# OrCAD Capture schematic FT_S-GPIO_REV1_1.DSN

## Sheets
1 INDEX: title: INDEX; rev: 1.0; note: 17 HaYetsira Street; note: Yokneam Illit, Israel 2069208
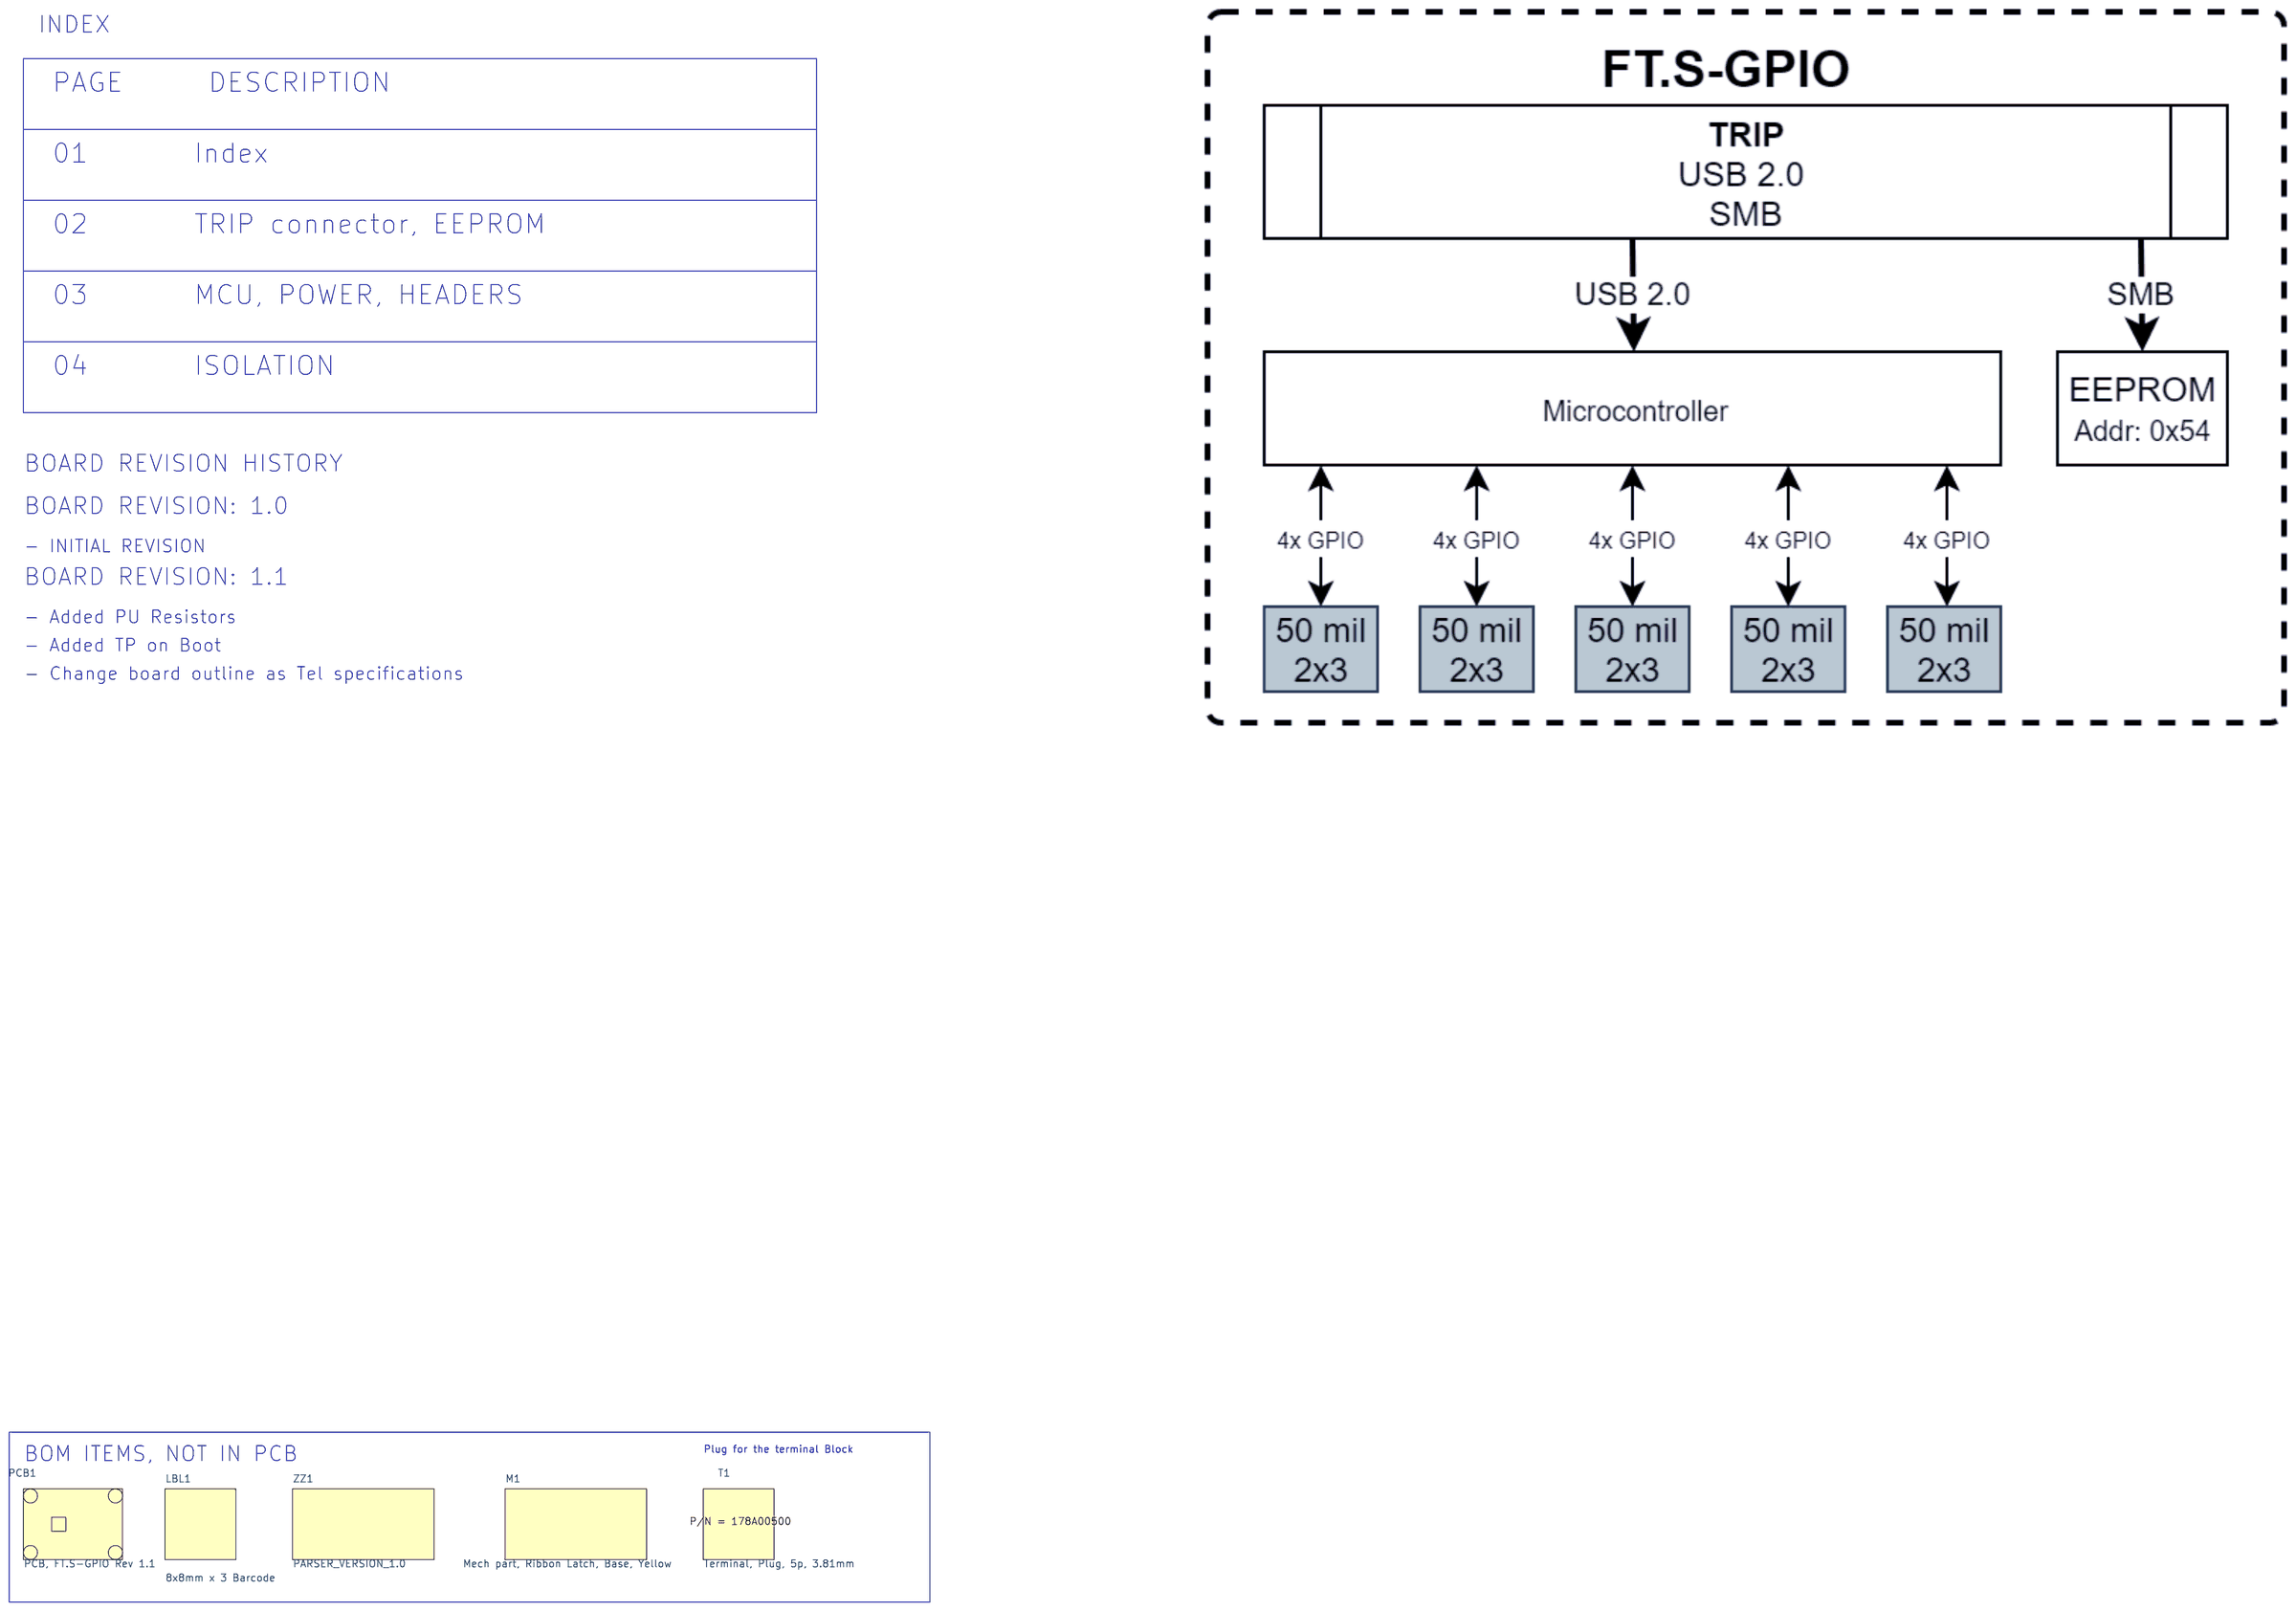
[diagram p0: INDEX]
2 CONN: size A3; title: 02- connector
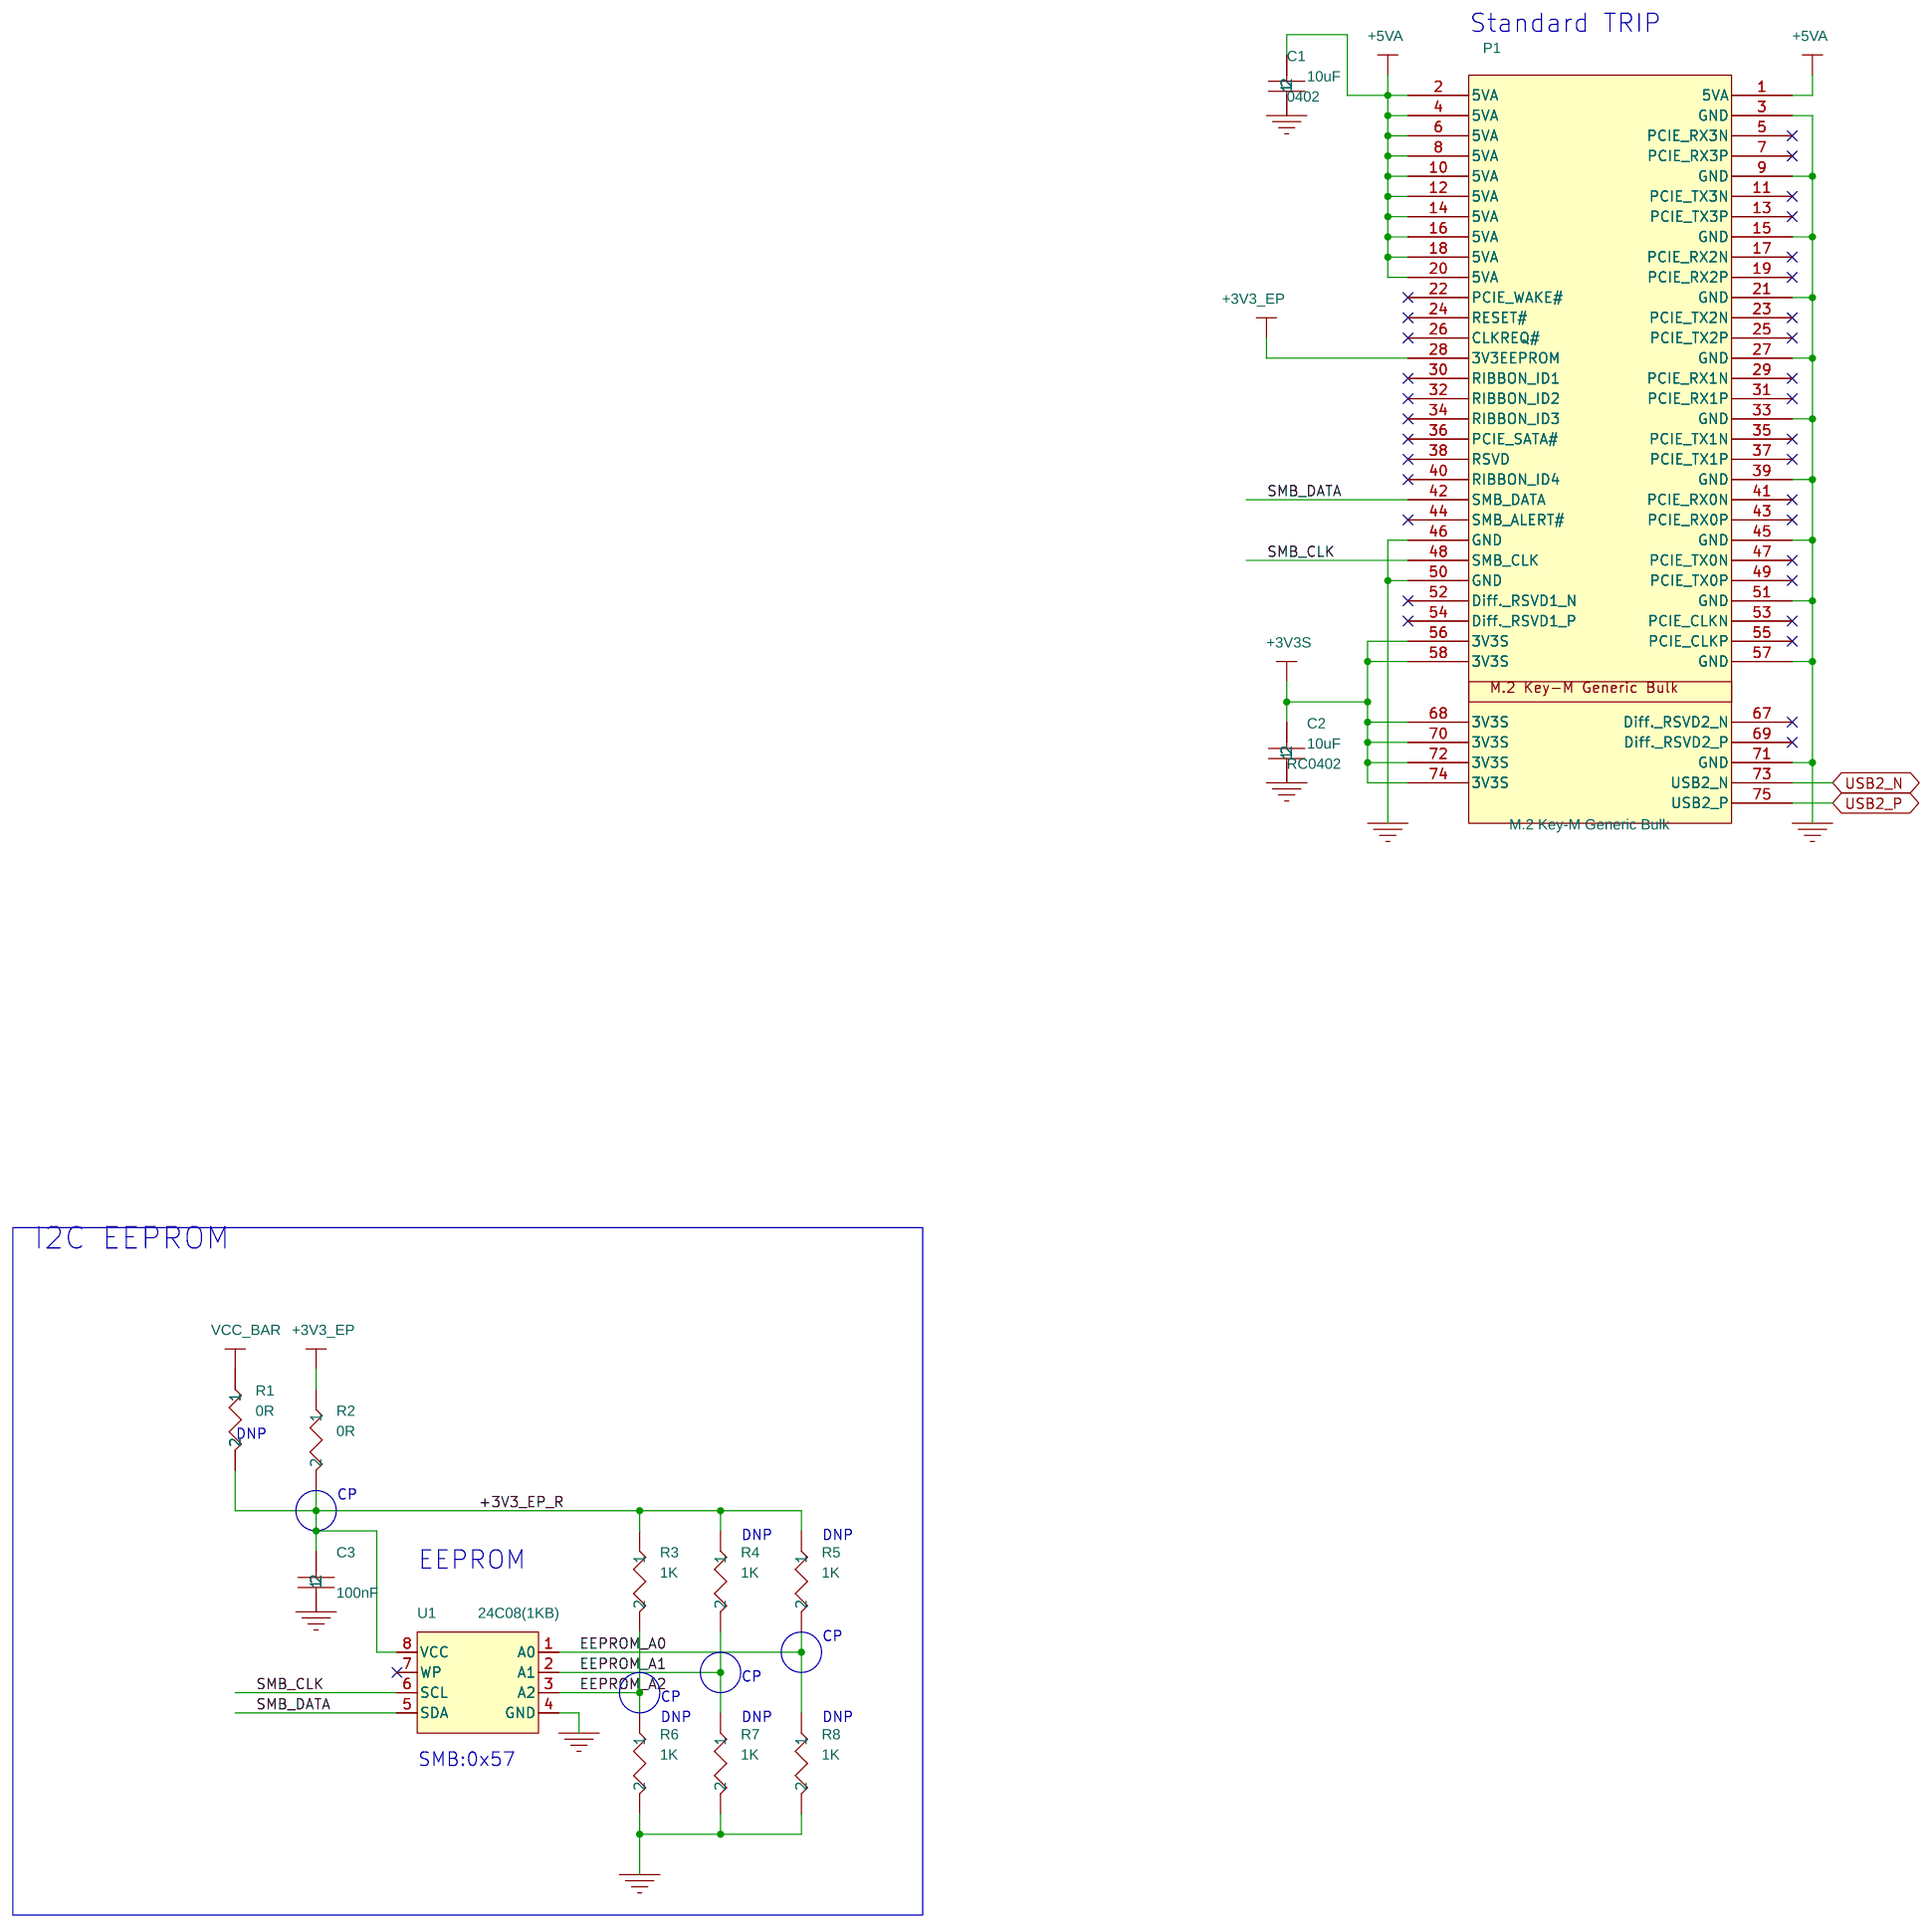
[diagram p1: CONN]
3 MCU: size A3; title: 03-MCU
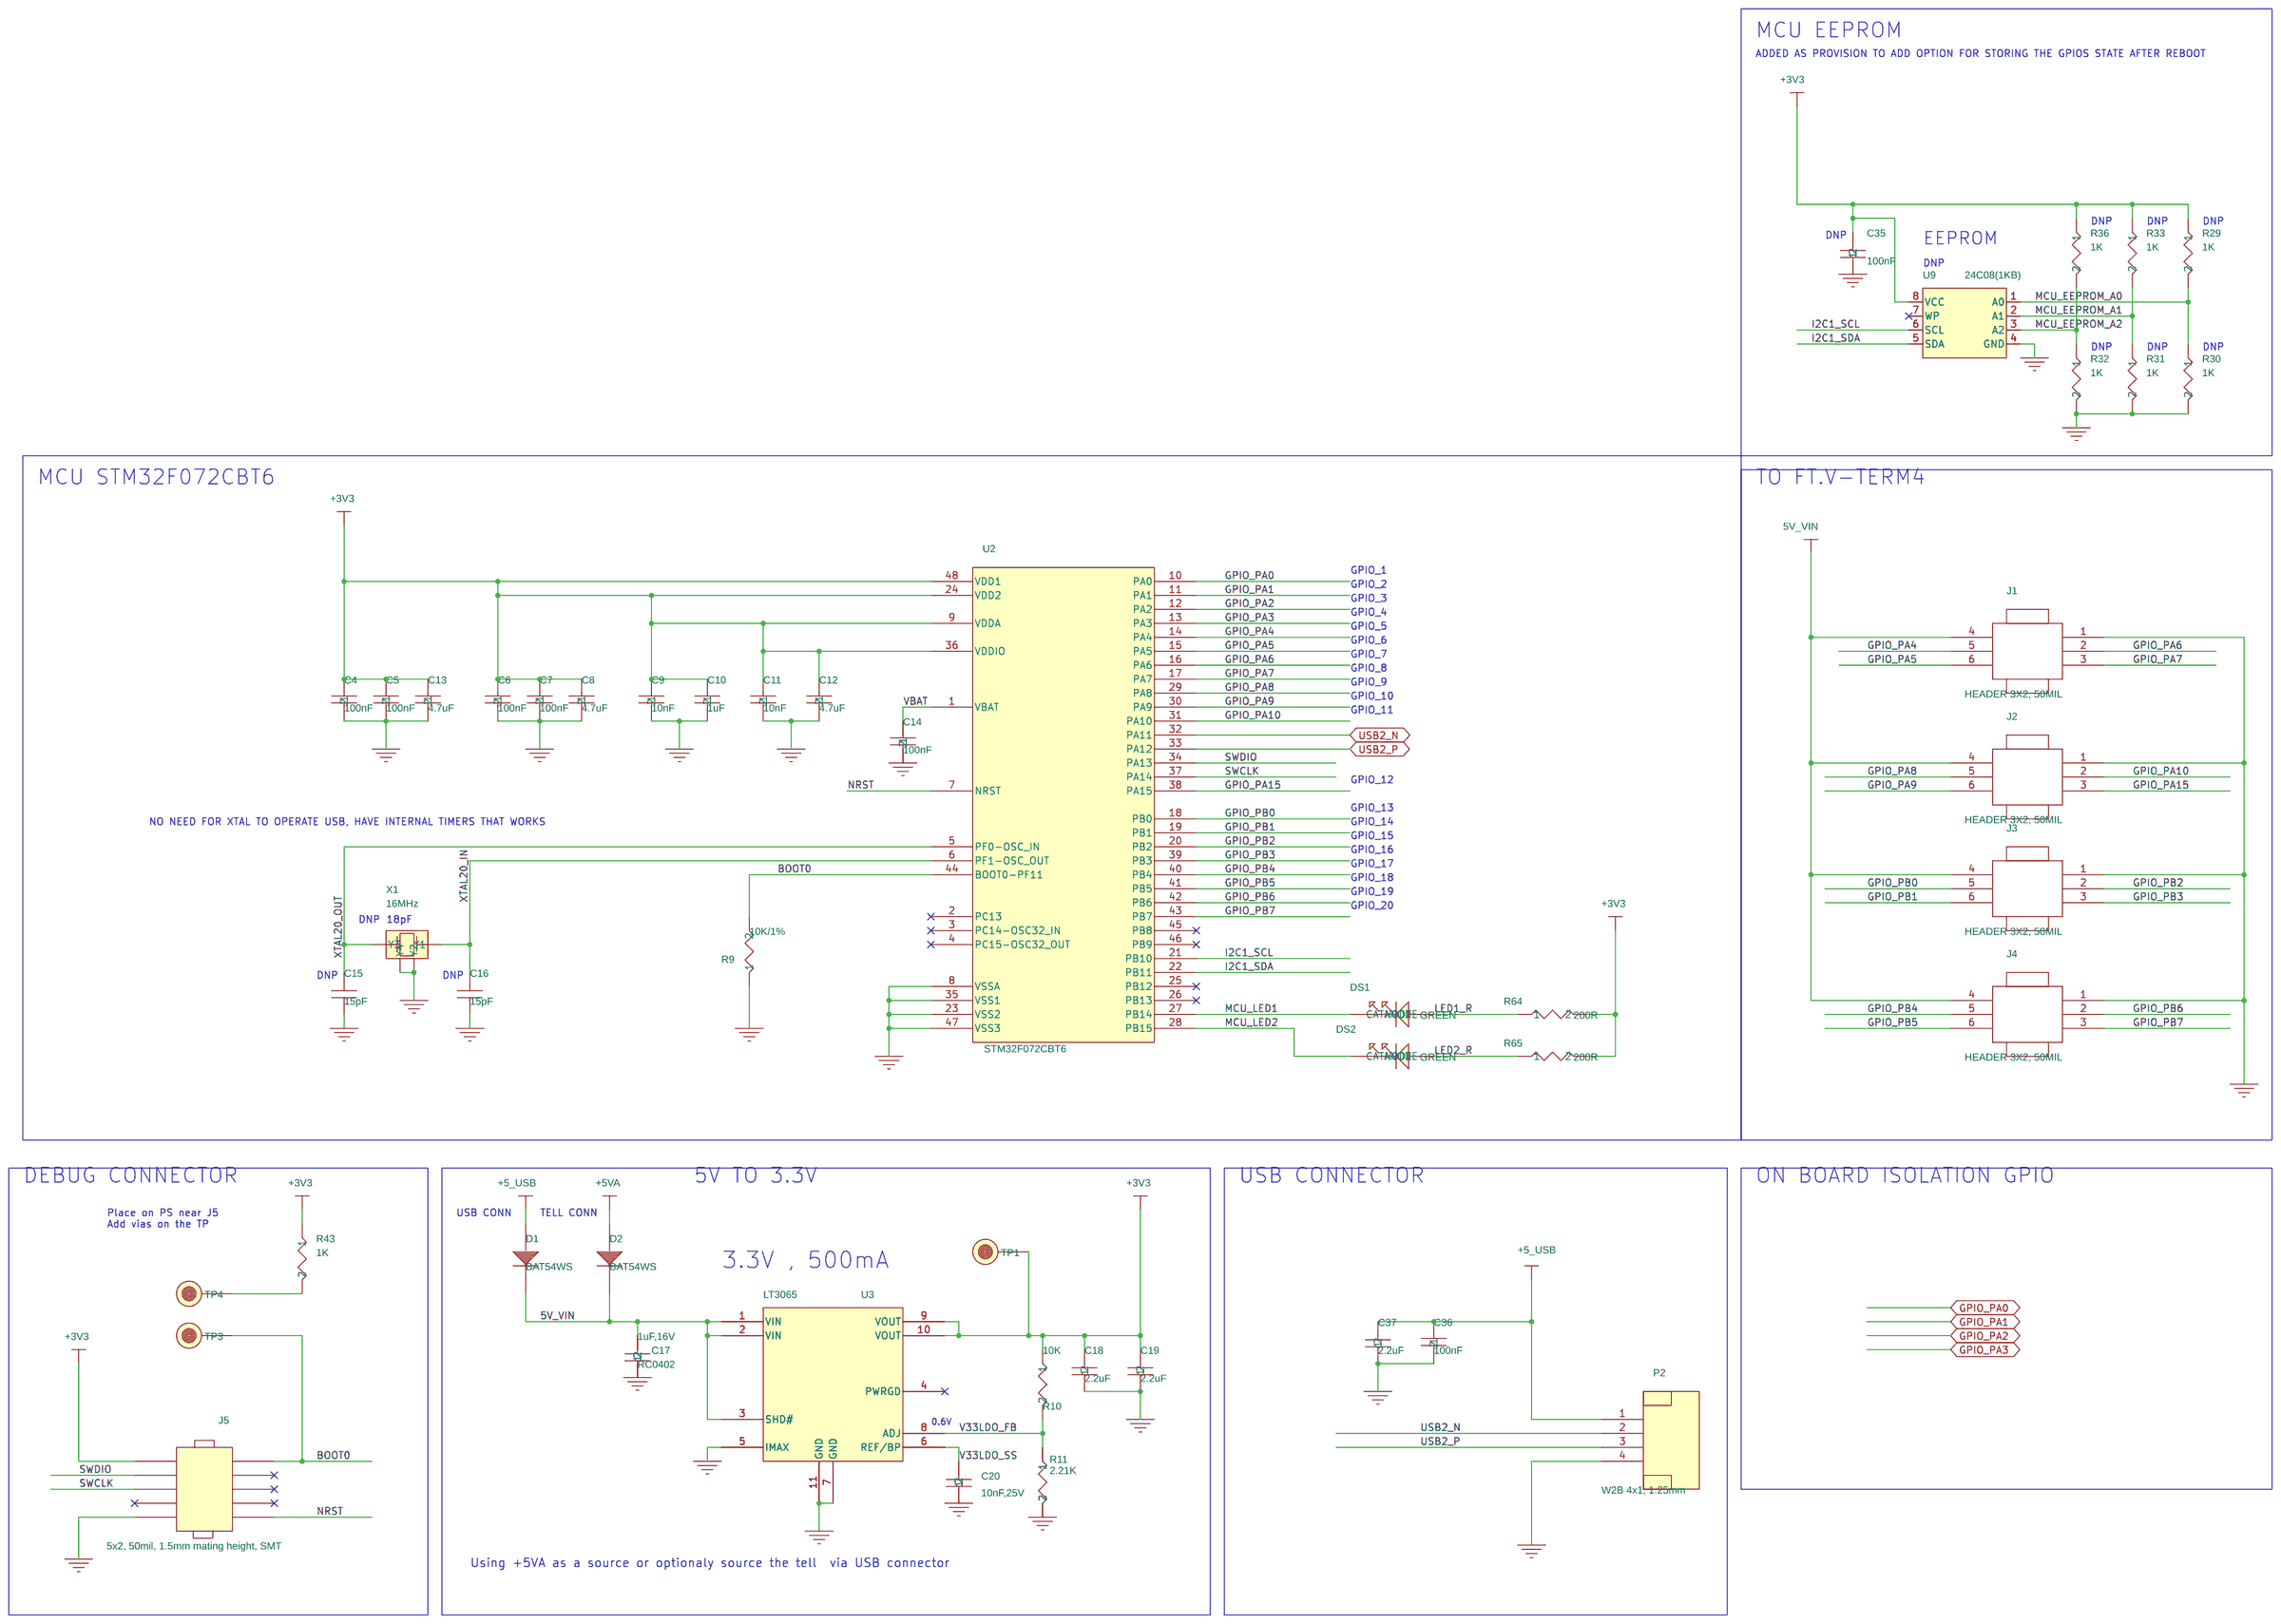
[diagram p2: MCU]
4 ISOLATION: size A3; title: 04 - ISOLATION
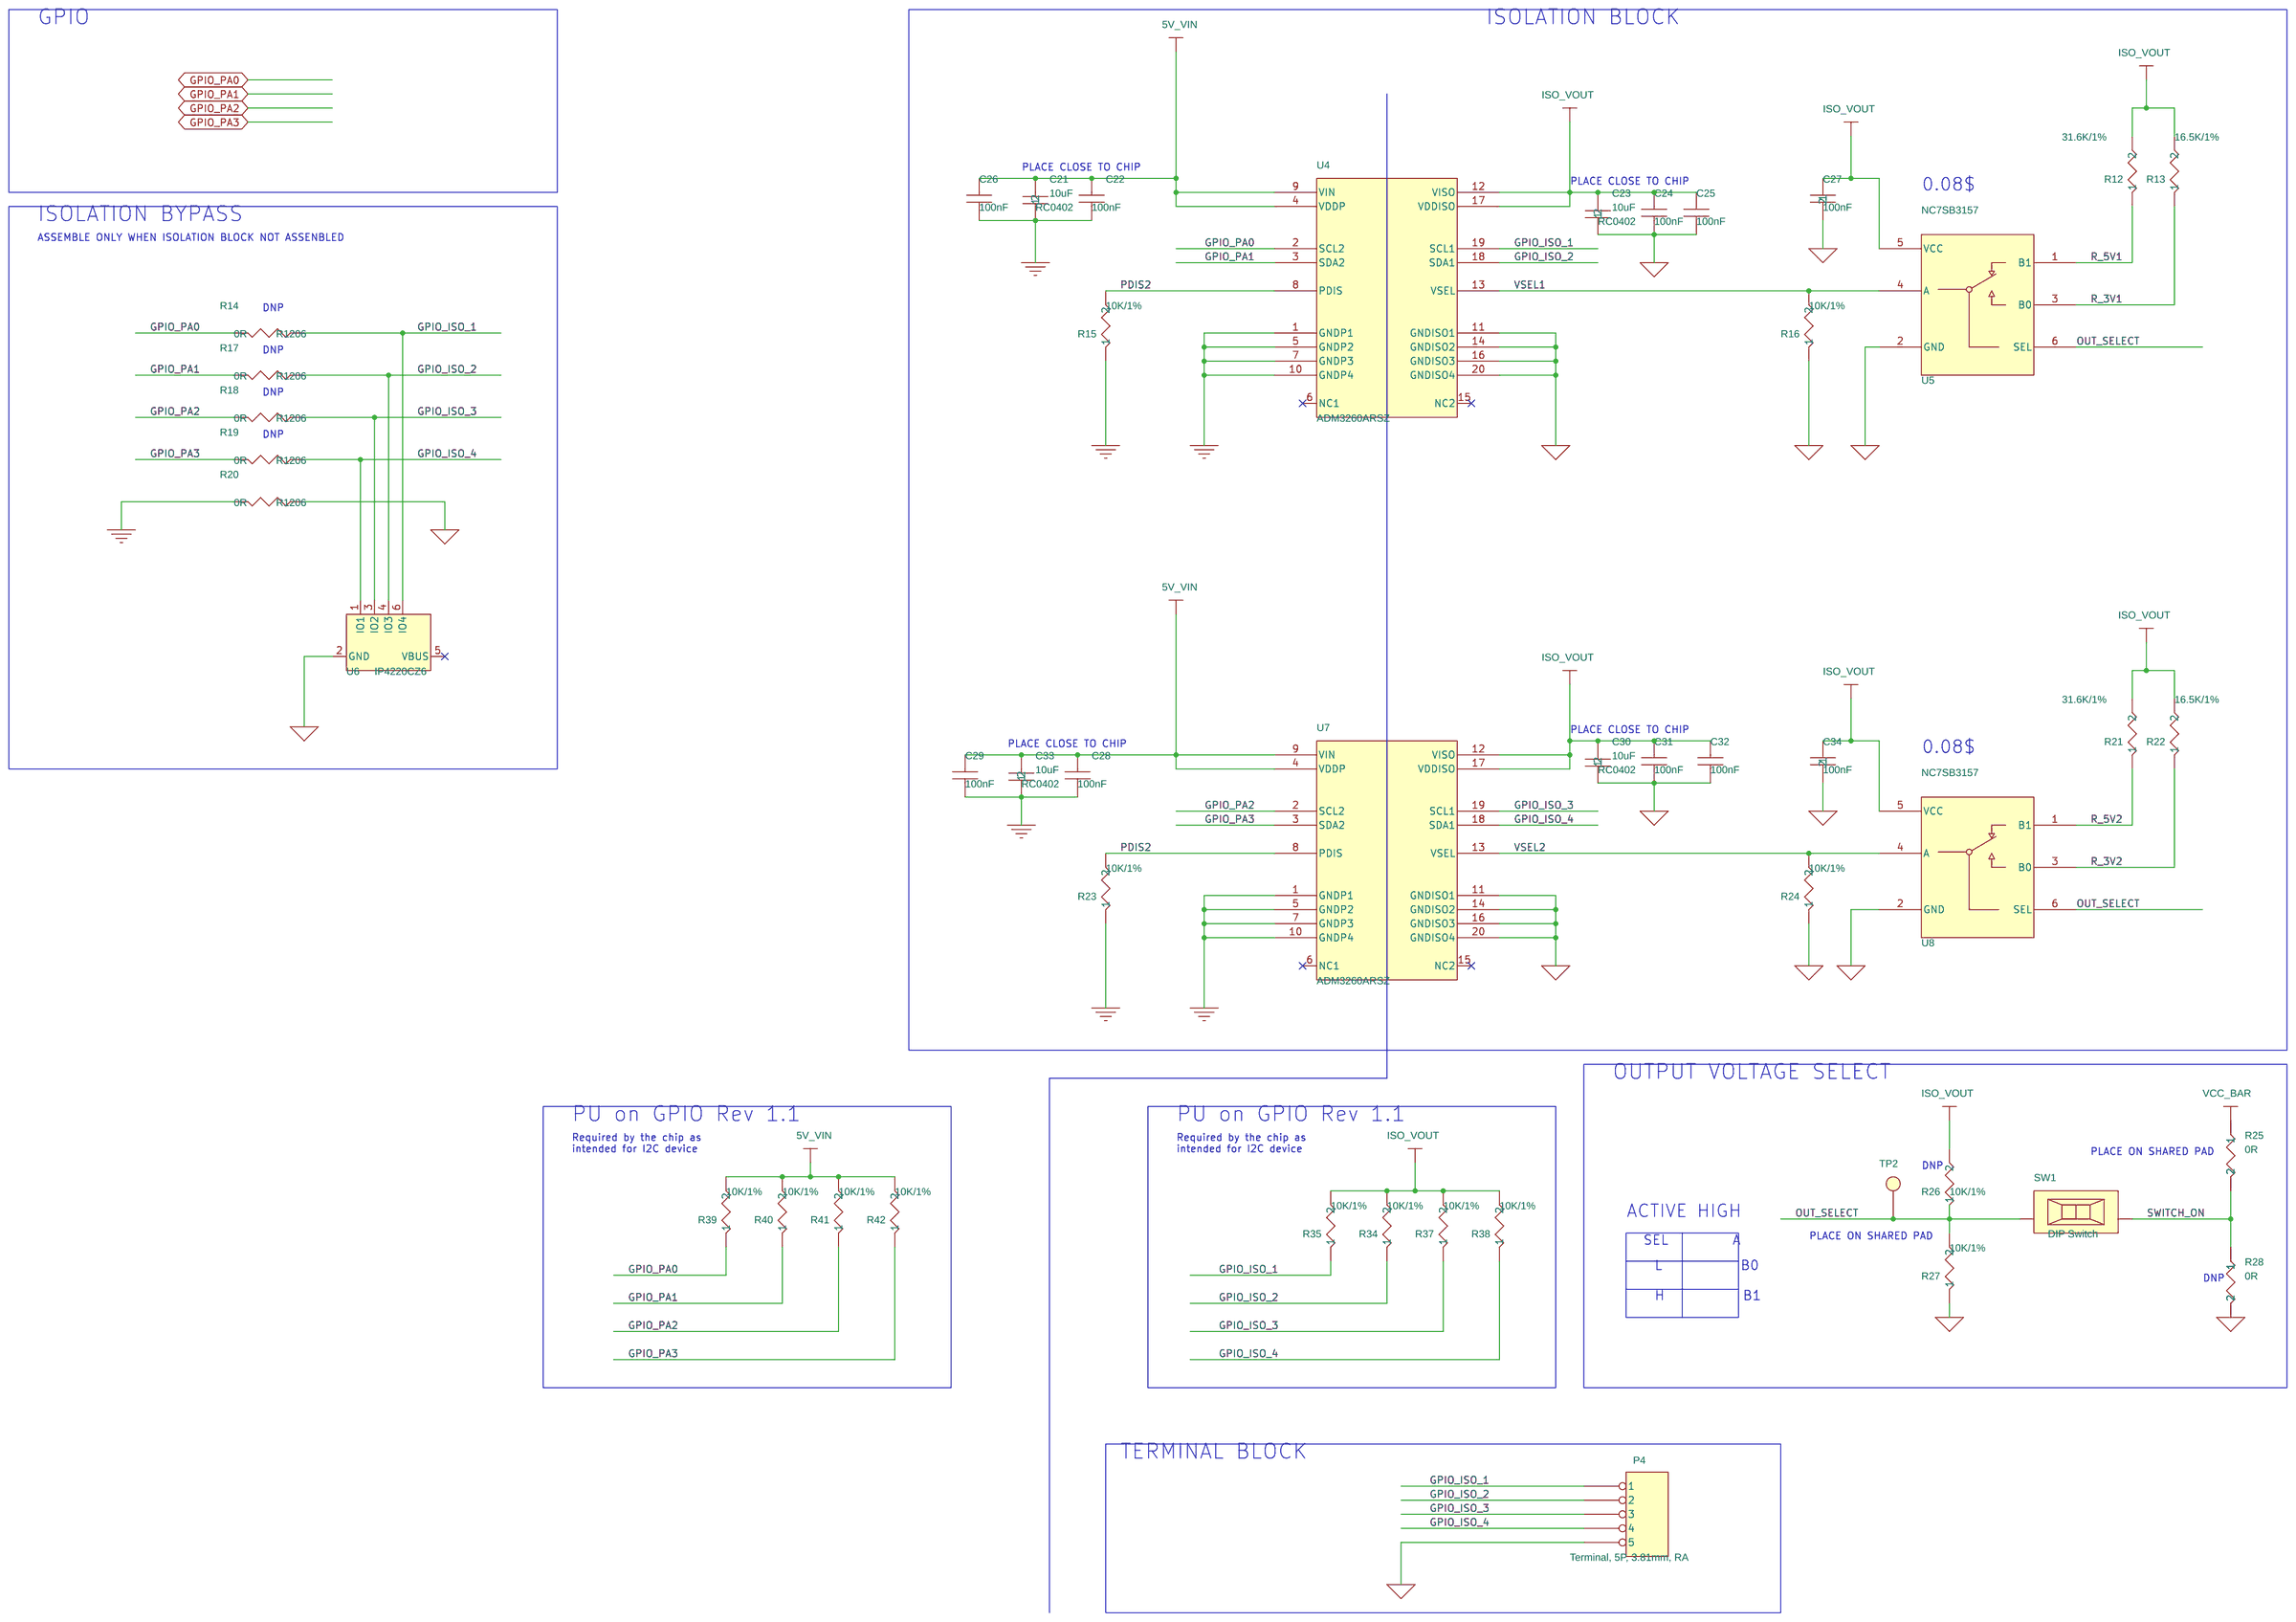
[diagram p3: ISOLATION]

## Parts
sheet CONN
C1  10uF  [0402]
C2  10uF  [RC0402]
C3  100nF  [RC0402]
P1  M.2 Key-M Generic Bulk  [NGFF67P8HMkeySM]
R1  0R  [RC0402]
R2  0R  [RC0402]
R3  1K  [RC0402]
R4  1K  [RC0402]
R5  1K  [RC0402]
R6  1K  [RC0402]
R7  1K  [RC0402]
R8  1K  [RC0402]
U1  24C08(1KB)  [MO-229VCED-2]
sheet INDEX
LBL1  8x8mm x 3 Barcode  [LBL XYU]
M1  Mech part, Ribbon Latch, Base, Yellow
PCB1  PCB, FT.S-GPIO Rev 1.1
T1  Terminal, Plug, 5p, 3.81mm
ZZ1  PARSER_VERSION_1.0
sheet ISOLATION
C21  10uF  [RC0402]
C22  100nF  [RC0402]
C23  10uF  [RC0402]
C24  100nF  [RC0402]
C25  100nF  [RC0402]
C26  100nF  [RC0402]
C27  100nF  [RC0402]
C28  100nF  [RC0402]
C29  100nF  [RC0402]
C30  10uF  [RC0402]
C31  100nF  [RC0402]
C32  100nF  [RC0402]
C33  10uF  [RC0402]
C34  100nF  [RC0402]
P4  Terminal, 5P, 3.81mm, RA  [TB3.81mmRA-5P]
R12  31.6K/1%  [RC0402]
R13  16.5K/1%  [RC0402]
R14  0R  [R1206]
R15  10K/1%  [RC0402]
R16  10K/1%  [RC0402]
R17  0R  [R1206]
R18  0R  [R1206]
R19  0R  [R1206]
R20  0R  [R1206]
R21  31.6K/1%  [RC0402]
R22  16.5K/1%  [RC0402]
R23  10K/1%  [RC0402]
R24  10K/1%  [RC0402]
R25  0R  [RC0402]
R26  10K/1%  [RC0402]
R27  10K/1%  [RC0402]
R28  0R  [RC0402]
R34  10K/1%  [RC0402]
R35  10K/1%  [RC0402]
R37  10K/1%  [RC0402]
R38  10K/1%  [RC0402]
R39  10K/1%  [RC0402]
R40  10K/1%  [RC0402]
R41  10K/1%  [RC0402]
R42  10K/1%  [RC0402]
SW1  DIP Switch  [SWDIP-1SM]
TP2  TP  [TP_TH_0p5mm]
U4  ADM3260ARSZ  [SSOP-20]
U5  NC7SB3157  [SC70-6]
U6  IP4220CZ6  [SOT23-6L]
U7  ADM3260ARSZ  [SSOP-20]
U8  NC7SB3157  [SC70-6]
sheet MCU
C4  100nF  [RC0402]
C5  100nF  [RC0402]
C6  100nF  [RC0402]
C7  100nF  [RC0402]
C8  4.7uF  [RC0402]
C9  10nF  [RC0402]
C10  1uF  [RC0402]
C11  10nF  [RC0402]
C12  4.7uF  [RC0402]
C13  4.7uF  [RC0402]
C14  100nF  [RC0402]
C15  15pF  [RC0402]
C16  15pF  [RC0402]
C17  1uF,16V  [RC0402]
C18  2.2uF  [RC0402]
C19  2.2uF  [RC0402]
C20  10nF,25V  [RC0402]
C35  100nF  [RC0402]
C36  100nF  [RC0402]
C37  2.2uF  [RC0402]
D1  BAT54WS  [SOD-323]
D2  BAT54WS  [SOD-323]
DS1  GREEN  [LED-0603]
DS2  GREEN  [LED-0603]
J1  HEADER 3X2, 50MIL  [2X3SMHDR50MIL]
J2  HEADER 3X2, 50MIL  [2X3SMHDR50MIL]
J3  HEADER 3X2, 50MIL  [2X3SMHDR50MIL]
J4  HEADER 3X2, 50MIL  [2X3SMHDR50MIL]
J5  5x2, 50mil, 1.5mm mating height, SMT  [2X5SMHDR]
P2  W2B 4x1, 1.25mm  [1x4W2B1_25RASM]
R9  10K/1%  [RC0402]
R10  10K  [RC0402]
R11  2.21K  [RC0402]
R29  1K  [RC0402]
R30  1K  [RC0402]
R31  1K  [RC0402]
R32  1K  [RC0402]
R33  1K  [RC0402]
R36  1K  [RC0402]
R43  1K  [RC0402]
R64  200R  [RC0402]
R65  200R  [RC0402]
TP1  TP
TP3  TP
TP4  TP
U2  STM32F072CBT6  [LQFP-48]
U3  LT3065  [DFN3x3-10]
U9  24C08(1KB)  [MO-229VCED-2]
X1  16MHz  [OSC3225]

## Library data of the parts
C1 C23 = 100nF,_10V,_X7R,_10%,_0402_1: CLABCONF0: =GPIO; P/N: 151B10600S
C2 C30 = 100nF,_10V,_X7R,_10%,_0402: CLABCONF0: =GPIO; P/N: 151B10600S
C3 = 15pF,_50V,_NPO,_5%,_0402: CLABCONF0: =GPIO; P/N: 151B10400S
P1 = M.2_Key-M_Generic_Bulk: CLABCONF0: =GPIO; P/N: 182K06700S
R1 = 348R,1%,0402,1_16W_3: CLABCONF0: =DNP; P/N: 161C00005S
R2 = 348R,1%,0402,1_16W_7: CLABCONF0: =GPIO; P/N: 161C00005S
R3 = 348R,1%,0402,1_16W_5: CLABCONF0: =GPIO; P/N: 161C10011S
R4 R30 = 348R,1%,0402,1_16W_1: CLABCONF0: =DNP; P/N: 161C10011S
R5 R36 = 348R,1%,0402,1_16W_2: CLABCONF0: =DNP; P/N: 161C10011S
R6 R32 = 348R,1%,0402,1_16W: CLABCONF0: =DNP; P/N: 161C10011S
R7 R29 = 348R,1%,0402,1_16W_6: CLABCONF0: =DNP; P/N: 161C10011S
R8 R31 = 348R,1%,0402,1_16W_4: CLABCONF0: =DNP; P/N: 161C10011S
U1 = 24C02,_serial_EE,_2KB,_I2C: CLABCONF0: =GPIO; P/N: 111S31000S
LBL1 = Label_8x8mm_x_3_for_Barcode: CLABCONF0: =GPIO
M1 = PARSER_VERSION_1_0.0: CLABCONF0: =GPIO; P/N: 290E010010
PCB1 = SBC-iHSW_Rev_1.0: CLABCONF0: =GPIO; P/N: TBD
T1 = Terminal,_Plug,_5p,_3.81mm: CLABCONF0: =GPIO
ZZ1 = PARSER_VERSION_1.0: CLABCONF0: =GPIO
C21 = 100nF,_10V,_X7R,_10%,_0402_5: CLABCONF0: =GPIO; P/N: 151B10600S
C22 C24-C26 C28 C29 C31 C32 = 100nF,_10V,_X7R,_10%,_0402_0: CLABCONF0: =GPIO; Group: LAN2
C27 = 100nF,_10V,_X7R,_10%,_0402_3: CLABCONF0: =GPIO
C33 = 100nF,_10V,_X7R,_10%,_0402_2: CLABCONF0: =GPIO; P/N: 151B10600S
C34 = 100nF,_10V,_X7R,_10%,_0402_4: CLABCONF0: =GPIO
P4 = Terminal,_5P,_3.81mm,_RA: CLABCONF0: =GPIO
R12 = 10K,1%,0402,1_16W_12: CLABCONF0: =GPIO; P/N: 161C31621S
R13 = 10K,1%,0402,1_16W_5: CLABCONF0: =GPIO; P/N: 161C16521S
R14 R17-R20 = 100K,_0402_0: CLABCONF0: =DNP; P/N: 161F00005S
R15 = 10K,1%,0402,1_16W_9: CLABCONF0: =GPIO
R16 = 10K,1%,0402,1_16W_15: CLABCONF0: =GPIO
R21 = 10K,1%,0402,1_16W_7: CLABCONF0: =GPIO; P/N: 161C31621S
R22 = 10K,1%,0402,1_16W: CLABCONF0: =GPIO; P/N: 161C16521S
R23 = 10K,1%,0402,1_16W_2: CLABCONF0: =GPIO
R24 = 10K,1%,0402,1_16W_17: CLABCONF0: =GPIO
R25 = 348R,1%,0402,1_16W: CLABCONF0: =GPIO; P/N: 161C00005S
R26 = 10K,1%,0402,1_16W_14: CLABCONF0: =DNP
R27 = 10K,1%,0402,1_16W_13: CLABCONF0: =GPIO
R28 = 348R,1%,0402,1_16W_1: CLABCONF0: =DNP; P/N: 161C00005S
R34 = 10K,1%,0402,1_16W_16: CLABCONF0: =GPIO
R35 = 10K,1%,0402,1_16W_10: CLABCONF0: =GPIO
R37 = 10K,1%,0402,1_16W_6: CLABCONF0: =GPIO
R38 = 10K,1%,0402,1_16W_3: CLABCONF0: =GPIO
R39 = 10K,1%,0402,1_16W_1: CLABCONF0: =GPIO
R40 = 10K,1%,0402,1_16W_11: CLABCONF0: =GPIO
R41 = 10K,1%,0402,1_16W_8: CLABCONF0: =GPIO
R42 = 10K,1%,0402,1_16W_4: CLABCONF0: =GPIO
SW1 = SW_DIP_Switch_x1: CLABCONF0: =GPIO; P/N: 170I30100S
TP2 = TP_SMT_0: CLABCONF0: =DNP
U4 U7 = ADM3260ARSZ: CLABCONF0: =GPIO
U5 U8 = Bus_switch_2_1: CLABCONF0: =GPIO
U6 = IP4220CZ6_0: CLABCONF0: =DNP; CLABCONF1: =MOCKUP
C4 = 100nF,_10V,_X7R,_10%,_0402_7: CLABCONF0: =GPIO
C5 = 100nF,_10V,_X7R,_10%,_0402_9: CLABCONF0: =GPIO
C6 = 100nF,_10V,_X7R,_10%,_0402_12: CLABCONF0: =GPIO
C7 = 100nF,_10V,_X7R,_10%,_0402_10: CLABCONF0: =GPIO
C8 = 100nF,_10V,_X7R,_10%,_0402_6: CLABCONF0: =GPIO; P/N: 151B47500S
C9 = 100nF,_10V,_X7R,_10%,_0402_14: CLABCONF0: =GPIO; P/N: 151C10300S
C10 = 100nF,_10V,_X7R,_10%,_0402_11: CLABCONF0: =GPIO; P/N: 151C10501S
C11 = 100nF,_10V,_X7R,_10%,_0402_8: CLABCONF0: =GPIO; P/N: 151C10300S
C12 = 100nF,_10V,_X7R,_10%,_0402_15: CLABCONF0: =GPIO; P/N: 151B47500S
C13 = 100nF,_10V,_X7R,_10%,_0402_4: CLABCONF0: =GPIO; P/N: 151B47500S
C14 = 100nF,_10V,_X7R,_10%,_0402_1: CLABCONF0: =GPIO
C15 C16 = 10pF,50V,NPO,_5%,_0402_0: CLABCONF0: =DNP; P/N: 151D15000S
C17 = 100nF,_10V,_X7R,_10%,_0402_2: CLABCONF0: =GPIO; P/N: 151C10500S
C18 = 100nF,_10V,_X7R,_10%,_0402_13: CLABCONF0: =GPIO; P/N: 151A22500S
C19 = 100nF,_10V,_X7R,_10%,_0402_16: CLABCONF0: =GPIO; P/N: 151A22500S
C20 = 100nF,_10V,_X7R,_10%,_0402: CLABCONF0: =GPIO; P/N: 151A22500S
C35 = 15pF,_50V,_NPO,_5%,_0402: CLABCONF0: =DNP; P/N: 151B10400S
C36 = 100nF,_10V,_X7R,_10%,_0402_5: CLABCONF0: =GPIO
C37 = 100nF,_10V,_X7R,_10%,_0402_3: CLABCONF0: =GPIO; P/N: 151A22500S
D1 D2 = BAT54WS: CLABCONF0: =GPIO
DS1 = LED-RED_1206_1: CLABCONF0: =GPIO; P/N: 139A10260S
DS2 = LED-RED_1206: CLABCONF0: =GPIO; P/N: 139A10260S
J1-J4 = HEADER_3X2,_50MIL: CLABCONF0: =GPIO; P/N: 190C00602S
J5 = HEADER_5x2_M_1: CLABCONF0: =DNP; P/N: 190C01002S
P2 = W2B_4x1_HDR,_1.25mm: CLABCONF0: =GPIO; P/N: 182E00401S
R9 = 10K,1%,0402,1_16W: CLABCONF0: =GPIO
R10 = 0R_1: CLABCONF0: =GPIO; P/N: 161C10021S
R11 = 0R_3: CLABCONF0: =GPIO; P/N: 161C22111S
R33 = 348R,1%,0402,1_16W_3: CLABCONF0: =DNP; P/N: 161C10011S
R43 = 348R,1%,0402,1_16W_5: CLABCONF0: =DNP; P/N: 161C10011S
R64 = 0R: CLABCONF0: =GPIO; P/N: 161C20001S
R65 = 0R_2: CLABCONF0: =GPIO; P/N: 161C20001S
TP1 TP3 TP4 = TP_SMT: CLABCONF0: =DNP
U2 = STM32F042C6T6: CLABCONF0: =GPIO; P/N: 115A01124S
U3 = LT3065_0: CLABCONF0: =GPIO; P/N: 123M0R601S
U9 = 24C02,_serial_EE,_2KB,_I2C: CLABCONF0: =DNP; P/N: 111S31000S
X1 = XTAL_25Mhz: CLABCONF0: =DNP; P/N: 141B16601S

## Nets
5V_VIN: C17.2 C21.2 C22.1 C26.1 C28.1 C29.1 C33.2 D1.CATHODE D2.CATHODE J1.4 J2.4 J3.4 J4.4 R39.2 R40.2 R41.2 R42.2 U3.1(VIN) U3.2(VIN) U3.3(SHD#) U4.4(VDDP) U4.9(VIN) U7.4(VDDP) U7.9(VIN)
+3V3: C4.1 C5.1 C6.1 C7.1 C8.1 C9.1 C10.1 C11.1 C12.1 C13.1 C18.2 C19.2 C35.2 J5.1 R10.1 R29.1 R33.1 R36.1 R43.1 R64.2 R65.2 TP1.1 U2.9(VDDA) U2.24(VDD2) U2.36(VDDIO) U2.48(VDD1) U3.9(VOUT) U3.10(VOUT) U9.8(VCC)
+3V3_EP: P1.28(3V3EEPROM) R2.1
+3V3_EP_R: C3.2 R1.2 R2.2 R3.1 R4.1 R5.1 U1.8(VCC)
+3V3S: C2.2 P1.56(3V3S) P1.58(3V3S) P1.68(3V3S) P1.70(3V3S) P1.72(3V3S) P1.74(3V3S) R1.1
+5VA: C1.2 D2.ANODE P1.1(5VA) P1.2(5VA) P1.4(5VA) P1.6(5VA) P1.8(5VA) P1.10(5VA) P1.12(5VA) P1.14(5VA) P1.16(5VA) P1.18(5VA) P1.20(5VA)
GND: C1.1 C2.1 C3.1 C4.2 C5.2 C6.2 C7.2 C8.2 C9.2 C10.2 C11.2 C12.2 C13.2 C14.2 C15.1 C16.1 C17.1 C18.1 C19.1 C20.1 C21.1 C22.2 C26.2 C28.2 C29.2 C33.1 C35.1 C36.2 C37.1 J1.1 J2.1 J3.1 J4.1 J5.5 P1.3(GND) P1.9(GND) P1.15(GND) P1.21(GND) P1.27(GND) P1.33(GND) P1.39(GND) P1.45(GND) P1.46(GND) P1.50(GND) P1.51(GND) P1.57(GND) P1.71(GND) P2.4 R6.2 R7.2 R8.2 R9.1 R11.2 R15.1 R20.2 R23.1 R30.2 R31.2 R32.2 U1.4(GND) U2.8(VSSA) U2.23(VSS2) U2.35(VSS1) U2.47(VSS3) U3.5(IMAX) U3.7(GND) U3.11(GND) U4.1(GNDP1) U4.5(GNDP2) U4.7(GNDP3) U4.10(GNDP4) U7.1(GNDP1) U7.5(GNDP2) U7.7(GNDP3) U7.10(GNDP4) U9.4(GND) X1.2(Y2) X1.4(Y4)
GND_ISO: C23.1 C24.2 C25.2 C27.2 C30.1 C31.2 C32.2 C34.2 P4.5 R16.1 R20.1 R24.1 R27.1 R28.2 U4.11(GNDISO1) U4.14(GNDISO2) U4.16(GNDISO3) U4.20(GNDISO4) U5.2(GND) U6.2(GND) U7.11(GNDISO1) U7.14(GNDISO2) U7.16(GNDISO3) U7.20(GNDISO4) U8.2(GND)
V33LDO_FB: R10.2 R11.1 U3.8(ADJ)
V33LDO_SS: C20.2 U3.6(REF/BP)
VBAT: C14.1 U2.1(VBAT)
+5_USB: C36.1 C37.2 D1.ANODE P2.1
BOOT0: J5.6 R9.2 TP3.1 U2.44(BOOT0-PF11)
EEPROM_A0: R5.2 R8.1 U1.1(A0)
EEPROM_A1: R4.2 R7.1 U1.2(A1)
EEPROM_A2: R3.2 R6.1 U1.3(A2)
GPIO_ISO_1: P4.1 R14.1 R35.1 U4.19(SCL1) U6.6(IO4)
GPIO_ISO_2: P4.2 R17.1 R34.1 U4.18(SDA1) U6.4(IO3)
GPIO_ISO_3: P4.3 R18.1 R37.1 U6.3(IO2) U7.19(SCL1)
GPIO_ISO_4: P4.4 R19.1 R38.1 U6.1(IO1) U7.18(SDA1)
GPIO_PA0: R14.2 R39.1 U2.10(PA0) U4.2(SCL2)
GPIO_PA1: R17.2 R40.1 U2.11(PA1) U4.3(SDA2)
GPIO_PA2: R18.2 R41.1 U2.12(PA2) U7.2(SCL2)
GPIO_PA3: R19.2 R42.1 U2.13(PA3) U7.3(SDA2)
GPIO_PA4: J1.5 U2.14(PA4)
GPIO_PA5: J1.6 U2.15(PA5)
GPIO_PA6: J1.2 U2.16(PA6)
GPIO_PA7: J1.3 U2.17(PA7)
GPIO_PA8: J2.5 U2.29(PA8)
GPIO_PA9: J2.6 U2.30(PA9)
GPIO_PA10: J2.2 U2.31(PA10)
GPIO_PA15: J2.3 U2.38(PA15)
GPIO_PB0: J3.5 U2.18(PB0)
GPIO_PB1: J3.6 U2.19(PB1)
GPIO_PB2: J3.2 U2.20(PB2)
GPIO_PB3: J3.3 U2.39(PB3)
GPIO_PB4: J4.5 U2.40(PB4)
GPIO_PB5: J4.6 U2.41(PB5)
GPIO_PB6: J4.2 U2.42(PB6)
GPIO_PB7: J4.3 U2.43(PB7)
I2C1_SCL: U2.21(PB10) U9.6(SCL)
I2C1_SDA: U2.22(PB11) U9.5(SDA)
ISO_VOUT: C23.2 C24.1 C25.1 C27.1 C30.2 C31.1 C32.1 C34.1 R12.2 R13.2 R21.2 R22.2 R25.1 R26.2 R34.2 R35.2 R37.2 R38.2 U4.12(VISO) U4.17(VDDISO) U5.5(VCC) U7.12(VISO) U7.17(VDDISO) U8.5(VCC)
LED1_R: DS1.ANODE R64.1
LED2_R: DS2.ANODE R65.1
MCU_EEPROM_A0: R29.2 R30.1 U9.1(A0)
MCU_EEPROM_A1: R31.1 R33.2 U9.2(A1)
MCU_EEPROM_A2: R32.1 R36.2 U9.3(A2)
MCU_LED1: DS1.CATHODE U2.27(PB14)
MCU_LED2: DS2.CATHODE U2.28(PB15)
NRST: J5.10 U2.7(NRST)
OUT_SELECT: R26.1 R27.2 SW1.1 TP2.1 U5.6(SEL) U8.6(SEL)
PDIS2: R15.2 R23.2 U4.8(PDIS) U7.8(PDIS)
R_3V1: R13.1 U5.3(B0)
R_3V2: R22.1 U8.3(B0)
R_5V1: R12.1 U5.1(B1)
R_5V2: R21.1 U8.1(B1)
SMB_CLK: P1.48(SMB_CLK) U1.6(SCL)
SMB_DATA: P1.42(SMB_DATA) U1.5(SDA)
SWCLK: J5.3 U2.37(PA14)
SWDIO: J5.2 U2.34(PA13)
SWITCH_ON: R25.2 R28.1 SW1.2
USB2_N: P1.73(USB2_N) P2.2 U2.32(PA11)
USB2_P: P1.75(USB2_P) P2.3 U2.33(PA12)
VSEL1: R16.2 U4.13(VSEL) U5.4(A)
VSEL2: R24.2 U7.13(VSEL) U8.4(A)
XTAL20_IN: C16.2 U2.6(PF1-OSC_OUT) X1.1(Y1)
XTAL20_OUT: C15.2 U2.5(PF0-OSC_IN) X1.3(Y3)
N16820631: R43.2 TP4.1

Not connected (* = marked no-connect by the designer): J5 4* 7* 8* 9*; P1 5(PCIE_RX3N)* 7(PCIE_RX3P)* 11(PCIE_TX3N)* 13(PCIE_TX3P)* 17(PCIE_RX2N)* 19(PCIE_RX2P)* 22(PCIE_WAKE#)* 23(PCIE_TX2N)* 24(RESET#)* 25(PCIE_TX2P)* 26(CLKREQ#)* 29(PCIE_RX1N)* 30(RIBBON_ID1)* 31(PCIE_RX1P)* 32(RIBBON_ID2)* 34(RIBBON_ID3)* 35(PCIE_TX1N)* 36(PCIE_SATA#)* 37(PCIE_TX1P)* 38(RSVD)* 40(RIBBON_ID4)* 41(PCIE_RX0N)* 43(PCIE_RX0P)* 44(SMB_ALERT#)* 47(PCIE_TX0N)* 49(PCIE_TX0P)* 52(Diff._RSVD1_N)* 53(PCIE_CLKN)* 54(Diff._RSVD1_P)* 55(PCIE_CLKP)* 67(Diff._RSVD2_N)* 69(Diff._RSVD2_P)*; U1 7(WP)*; U2 2(PC13)* 3(PC14-OSC32_IN)* 4(PC15-OSC32_OUT)* 25(PB12)* 26(PB13)* 45(PB8)* 46(PB9)*; U3 4(PWRGD)*; U4 6(NC1)* 15(NC2)*; U6 5(VBUS)*; U7 6(NC1)* 15(NC2)*; U9 7(WP)*

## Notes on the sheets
sheet 1
- INDEX
- PAGE
- DESCRIPTION
- 01
- Index
- 02
- TRIP connector, EEPROM
- 03
- MCU, POWER, HEADERS
- 04
- ISOLATION
- BOARD REVISION HISTORY
- BOARD REVISION: 1.0
- - INITIAL REVISION
- BOARD REVISION: 1.1
- - Added PU Resistors
- - Added TP on Boot
- - Change board outline as Tel specifications
- BOM ITEMS, NOT IN PCB
- Plug for the terminal Block
sheet 2
- Standard TRIP
- I2C EEPROM
- DNP
- CP
- DNP
- DNP
- EEPROM
- CP
- CP
- CP
- DNP
- DNP
- DNP
- SMB:0x57
sheet 3
- MCU EEPROM
- ADDED AS PROVISION TO ADD OPTION FOR STORING THE GPIOS STATE AFTER REBOOT
- DNP
- DNP
- DNP
- DNP
- EEPROM
- DNP
- DNP
- DNP
- DNP
- MCU STM32F072CBT6
- TO FT.V-TERM4
- GPIO_1
- GPIO_2
- GPIO_3
- GPIO_4
- GPIO_5
- GPIO_6
- GPIO_7
- GPIO_8
- GPIO_9
- GPIO_10
- GPIO_11
- GPIO_12
- GPIO_13
- NO NEED FOR XTAL TO OPERATE USB, HAVE INTERNAL TIMERS THAT WORKS
- GPIO_14
- GPIO_15
- GPIO_16
- GPIO_17
- GPIO_18
- GPIO_19
- GPIO_20
- DNP
- 18pF
- DNP
- DNP
- DEBUG CONNECTOR
- 5V TO 3.3V
- USB CONNECTOR
- ON BOARD ISOLATION GPIO
- Place on PS near J5
  Add vias on the TP
- USB CONN
- TELL CONN
- 3.3V , 500mA
- 0.6V
- Using +5VA as a source or optionaly source the tell  via USB connector
sheet 4
- GPIO
- ISOLATION BLOCK
- PLACE CLOSE TO CHIP
- PLACE CLOSE TO CHIP
- 0.08$
- ISOLATION BYPASS
- ASSEMBLE ONLY WHEN ISOLATION BLOCK NOT ASSENBLED
- DNP
- DNP
- DNP
- DNP
- PLACE CLOSE TO CHIP
- PLACE CLOSE TO CHIP
- 0.08$
- OUTPUT VOLTAGE SELECT
- PU on GPIO Rev 1.1
- PU on GPIO Rev 1.1
- Required by the chip as
  intended for I2C device
- Required by the chip as
  intended for I2C device
- PLACE ON SHARED PAD
- DNP
- ACTIVE HIGH
- SEL         A
- PLACE ON SHARED PAD
- L           B0
  H           B1
- DNP
- TERMINAL BLOCK
